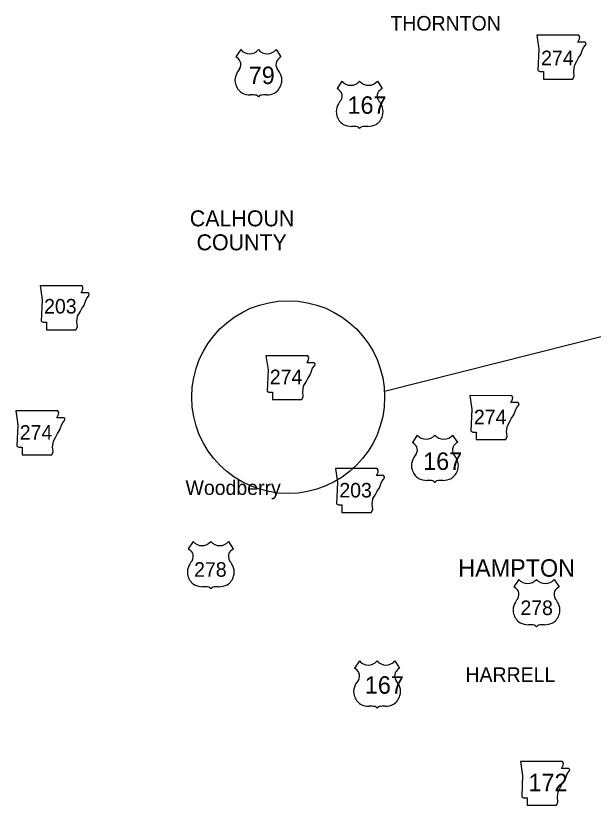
# Model space of a CAD drawing. Extents: x 172 to 3385, y 73 to 2074.
# Drawn here: x 198 to 834, y 1117 to 1987 of the extents above; entities that cross this region are included whole.
import ezdxf

# ---------------------------------------------------------------- set-up
doc = ezdxf.new("R2010")
doc.units = 0
for name, color, linetype in [('G-ANNO-NPLT', 7, 'Continuous'), ('Level 21', 7, 'Continuous'), ('Level 22', 7, 'Continuous'), ('Level 24', 7, 'Continuous'), ('R_Border', 7, 'Continuous'), ('R_Border Prem', 7, 'Continuous')]:
    doc.layers.add(name, color=color, linetype=linetype)

msp = doc.modelspace()

# ---------------------------------------------------------------- linework, layer by layer
at = {"layer": 'Level 21'}
for points in [[(771.57, 1965.87), (773.89, 1950.45), (772.86, 1927.07), (774.91, 1925.79), (778.77, 1925.79), (778.77, 1917.56), (811.15, 1917.56), (812.69, 1920.9), (812.17, 1926.3), (812.95, 1932.47), (815.77, 1937.35), (817.57, 1940.95), (820.14, 1944.8), (821.68, 1948.91), (822.97, 1952.25), (825.28, 1955.08), (825.79, 1956.88), (824.77, 1958.16), (816.8, 1958.16), (818.6, 1961.76), (818.86, 1964.07), (817.79, 1965.85)], [(224.33, 1689.68), (226.64, 1674.26), (225.61, 1650.88), (227.67, 1649.59), (231.52, 1649.59), (231.52, 1641.37), (263.9, 1641.37), (265.44, 1644.71), (264.93, 1650.11), (265.7, 1656.28), (268.53, 1661.16), (270.33, 1664.76), (272.9, 1668.61), (274.44, 1672.72), (275.72, 1676.06), (278.03, 1678.89), (278.55, 1680.69), (277.52, 1681.97), (269.55, 1681.97), (271.35, 1685.57), (271.61, 1687.88), (270.54, 1689.66)], [(473.18, 1612.6), (475.49, 1597.18), (474.46, 1573.8), (476.52, 1572.51), (480.37, 1572.51), (480.37, 1564.29), (512.75, 1564.29), (514.29, 1567.63), (513.78, 1573.03), (514.55, 1579.19), (517.37, 1584.07), (519.17, 1587.67), (521.74, 1591.53), (523.29, 1595.64), (524.57, 1598.98), (526.88, 1601.81), (527.4, 1603.6), (526.37, 1604.89), (518.4, 1604.89), (520.2, 1608.49), (520.46, 1610.8), (519.39, 1612.58)], [(697.73, 1568.72), (700.04, 1553.3), (699.01, 1529.92), (701.07, 1528.63), (704.92, 1528.63), (704.92, 1520.41), (737.3, 1520.41), (738.84, 1523.75), (738.33, 1529.14), (739.1, 1535.31), (741.93, 1540.19), (743.72, 1543.79), (746.29, 1547.65), (747.84, 1551.76), (749.12, 1555.1), (751.43, 1557.92), (751.95, 1559.72), (750.92, 1561.01), (742.95, 1561.01), (744.75, 1564.61), (745.01, 1566.92), (743.94, 1568.69)], [(197.6, 1551.94), (199.91, 1536.53), (198.89, 1513.14), (200.94, 1511.86), (204.8, 1511.86), (204.8, 1503.63), (237.17, 1503.63), (238.72, 1506.97), (238.2, 1512.37), (238.97, 1518.54), (241.8, 1523.42), (243.6, 1527.02), (246.17, 1530.87), (247.71, 1534.98), (248.99, 1538.32), (251.31, 1541.15), (251.82, 1542.95), (250.79, 1544.23), (242.83, 1544.23), (244.63, 1547.83), (244.88, 1550.14), (243.82, 1551.92)], [(549.65, 1488.36), (551.97, 1472.94), (550.94, 1449.56), (552.99, 1448.28), (556.85, 1448.28), (556.85, 1440.05), (589.23, 1440.05), (590.77, 1443.39), (590.25, 1448.79), (591.02, 1454.96), (593.85, 1459.84), (595.65, 1463.44), (598.22, 1467.29), (599.76, 1471.4), (601.05, 1474.74), (603.36, 1477.57), (603.87, 1479.37), (602.84, 1480.65), (594.88, 1480.65), (596.68, 1484.25), (596.93, 1486.56), (595.87, 1488.34)], [(753.63, 1165.68), (755.94, 1150.26), (754.91, 1126.88), (756.97, 1125.59), (760.82, 1125.59), (760.82, 1117.37), (793.2, 1117.37), (794.74, 1120.71), (794.23, 1126.11), (795, 1132.28), (797.83, 1137.16), (799.63, 1140.76), (802.2, 1144.61), (803.74, 1148.72), (805.02, 1152.06), (807.33, 1154.89), (807.85, 1156.69), (806.82, 1157.97), (798.85, 1157.97), (800.65, 1161.57), (800.91, 1163.88), (799.84, 1165.66)]]:
    msp.add_lwpolyline(points, close=True, dxfattribs=at)
at = {"layer": 'Level 22'}
for p, q in [((445.33, 1950.07), (440.07, 1941.94)), ((484.43, 1950.07), (489.68, 1941.94)), ((556.86, 1915.29), (551.6, 1907.15)), ((595.95, 1915.29), (601.21, 1907.15)), ((639.77, 1525.26), (634.51, 1517.13)), ((678.86, 1525.26), (684.12, 1517.13)), ((392.89, 1408), (387.63, 1399.87)), ((431.98, 1408), (437.24, 1399.87)), ((751.66, 1366.17), (746.4, 1358.03)), ((790.75, 1366.17), (796.01, 1358.03)), ((576.06, 1276.39), (570.8, 1268.25)), ((615.15, 1276.39), (620.41, 1268.25))]:
    msp.add_line(p, q, dxfattribs=at)
for centre, radius, start, end in [((455.12, 1958.31), 12.8, 220.07504, 319.67012), ((474.63, 1958.31), 12.8, 220.32988, 319.92496), ((433.2, 1930.13), 13.66, 30.7809, 59.98827), ((496.55, 1930.13), 13.66, 120.01173, 149.2191), ((436.21, 1933.74), 9.36, 328.81046, 21.21077), ((493.55, 1933.74), 9.36, 158.78923, 211.18954), ((460.7, 1914.54), 21.85, 138.95648, 162.69135), ((469.06, 1914.54), 21.85, 17.30865, 41.04352), ((453.49, 1916.33), 14.44, 160.95764, 197.38186), ((476.27, 1916.33), 14.44, 342.61814, 19.04236), ((566.65, 1923.52), 12.8, 220.07504, 319.67012), ((586.16, 1923.52), 12.8, 220.32988, 319.92496), ((455.84, 1916.37), 16.7, 195.10743, 237.13119), ((473.92, 1916.37), 16.7, 302.86881, 344.89257), ((544.73, 1895.35), 13.66, 30.7809, 59.98827), ((608.08, 1895.35), 13.66, 120.01173, 149.2191), ((456.15, 1921.63), 21.45, 244.07708, 269.57785), ((456.64, 1860.9), 39.29, 81.19416, 90.95387), ((461.56, 1896.13), 3.76, 28.03422, 72.98637), ((468.2, 1896.13), 3.76, 107.01363, 151.96578), ((473.11, 1860.9), 39.29, 89.04613, 98.80584), ((473.61, 1921.63), 21.45, 270.42215, 295.92292), ((547.73, 1898.95), 9.36, 328.81046, 21.21077), ((605.07, 1898.95), 9.36, 158.78923, 211.18954), ((572.22, 1879.76), 21.85, 138.95648, 162.69135), ((580.58, 1879.76), 21.85, 17.30865, 41.04352), ((565.01, 1881.55), 14.44, 160.95764, 197.38186), ((587.8, 1881.55), 14.44, 342.61814, 19.04236), ((567.36, 1881.59), 16.7, 195.10743, 237.13119), ((585.45, 1881.59), 16.7, 302.86881, 344.89257), ((567.67, 1886.85), 21.45, 244.07708, 269.57785), ((568.17, 1826.12), 39.29, 81.19416, 90.95387), ((573.08, 1861.34), 3.76, 28.03422, 72.98637), ((579.73, 1861.34), 3.76, 107.01363, 151.96578), ((584.64, 1826.12), 39.29, 89.04613, 98.80584), ((585.13, 1886.85), 21.45, 270.42215, 295.92292), ((649.56, 1533.5), 12.8, 220.07504, 319.67012), ((669.07, 1533.5), 12.8, 220.32988, 319.92496), ((627.64, 1505.33), 13.66, 30.7809, 59.98827), ((690.99, 1505.33), 13.66, 120.01173, 149.2191), ((630.65, 1508.93), 9.36, 328.81046, 21.21077), ((687.98, 1508.93), 9.36, 158.78923, 211.18954), ((655.13, 1489.73), 21.85, 138.95648, 162.69135), ((663.5, 1489.73), 21.85, 17.30865, 41.04352), ((647.92, 1491.52), 14.44, 160.95764, 197.38186), ((670.71, 1491.52), 14.44, 342.61814, 19.04236), ((650.27, 1491.57), 16.7, 195.10743, 237.13119), ((668.36, 1491.57), 16.7, 302.86881, 344.89257), ((650.58, 1496.83), 21.45, 244.07708, 269.57785), ((651.08, 1436.1), 39.29, 81.19416, 90.95387), ((655.99, 1471.32), 3.76, 28.03422, 72.98637), ((662.64, 1471.32), 3.76, 107.01363, 151.96578), ((667.55, 1436.1), 39.29, 89.04613, 98.80584), ((668.05, 1496.83), 21.45, 270.42215, 295.92292), ((402.68, 1416.24), 12.8, 220.07504, 319.67012), ((422.19, 1416.24), 12.8, 220.32988, 319.92496), ((380.76, 1388.07), 13.66, 30.7809, 59.98827), ((383.77, 1391.67), 9.36, 328.81046, 21.21077), ((441.11, 1391.67), 9.36, 158.78923, 211.18954), ((444.11, 1388.07), 13.66, 120.01173, 149.2191), ((408.25, 1372.47), 21.85, 138.95648, 162.69135), ((416.62, 1372.47), 21.85, 17.30865, 41.04352), ((401.04, 1374.26), 14.44, 160.95764, 197.38186), ((423.83, 1374.26), 14.44, 342.61814, 19.04236), ((403.39, 1374.31), 16.7, 195.10743, 237.13119), ((421.48, 1374.31), 16.7, 302.86881, 344.89257), ((761.45, 1374.4), 12.8, 220.07504, 319.67012), ((780.96, 1374.4), 12.8, 220.32988, 319.92496), ((403.7, 1379.57), 21.45, 244.07708, 269.57785), ((404.2, 1318.84), 39.29, 81.19416, 90.95387), ((409.11, 1354.06), 3.76, 28.03422, 72.98637), ((415.76, 1354.06), 3.76, 107.01363, 151.96578), ((420.67, 1318.84), 39.29, 89.04613, 98.80584), ((421.17, 1379.57), 21.45, 270.42215, 295.92292), ((739.53, 1346.23), 13.66, 30.7809, 59.98827), ((802.88, 1346.23), 13.66, 120.01173, 149.2191), ((742.53, 1349.83), 9.36, 328.81046, 21.21077), ((799.87, 1349.83), 9.36, 158.78923, 211.18954), ((767.02, 1330.64), 21.85, 138.95648, 162.69135), ((775.38, 1330.64), 21.85, 17.30865, 41.04352), ((759.81, 1332.43), 14.44, 160.95764, 197.38186), ((782.6, 1332.43), 14.44, 342.61814, 19.04236), ((762.16, 1332.47), 16.7, 195.10743, 237.13119), ((780.25, 1332.47), 16.7, 302.86881, 344.89257), ((762.47, 1337.73), 21.45, 244.07708, 269.57785), ((762.97, 1277), 39.29, 81.19416, 90.95387), ((767.88, 1312.22), 3.76, 28.03422, 72.98637), ((774.53, 1312.22), 3.76, 107.01363, 151.96578), ((779.44, 1277), 39.29, 89.04613, 98.80584), ((779.93, 1337.73), 21.45, 270.42215, 295.92292), ((585.85, 1284.62), 12.8, 220.07504, 319.67012), ((605.36, 1284.62), 12.8, 220.32988, 319.92496), ((563.93, 1256.45), 13.66, 30.7809, 59.98827), ((566.94, 1260.05), 9.36, 328.81046, 21.21077), ((624.28, 1260.05), 9.36, 158.78923, 211.18954), ((627.28, 1256.45), 13.66, 120.01173, 149.2191), ((591.43, 1240.86), 21.85, 138.95648, 162.69135), ((599.79, 1240.86), 21.85, 17.30865, 41.04352), ((584.21, 1242.65), 14.44, 160.95764, 197.38186), ((607, 1242.65), 14.44, 342.61814, 19.04236), ((586.56, 1242.69), 16.7, 195.10743, 237.13119), ((604.65, 1242.69), 16.7, 302.86881, 344.89257), ((586.88, 1247.95), 21.45, 244.07708, 269.57785), ((604.34, 1247.95), 21.45, 270.42215, 295.92292), ((587.37, 1187.22), 39.29, 81.19416, 90.95387), ((592.28, 1222.44), 3.76, 28.03422, 72.98637), ((598.93, 1222.44), 3.76, 107.01363, 151.96578), ((603.84, 1187.22), 39.29, 89.04613, 98.80584)]:
    msp.add_arc(centre, radius, start, end, dxfattribs=at)
at = {"layer": 'R_Border Prem'}
msp.add_lwpolyline([(603.86, 1573.8), (1018.61, 1678.41), (1236.26, 1678.41)], dxfattribs=at)
msp.add_circle((497.68, 1567.07), 106.26, dxfattribs=at)

# ---------------------------------------------------------------- texts
at = {"layer": 'G-ANNO-NPLT'}
for s, height, p in [('THORNTON', 16.04, (610.31, 1971.05)), ('HAMPTON', 19.247, (684.97, 1369.18)), ('HARRELL', 16.04, (692.96, 1253.31))]:
    msp.add_text(s, height=height, dxfattribs=at).set_placement(p)
at = {"layer": 'Level 21'}
for s, height, p in [('274', 16.04, (776.33, 1932.88)), ('203', 16.04, (228.79, 1659.22)), ('274', 16.04, (477.44, 1581.34)), ('274', 16.04, (702.29, 1537.14)), ('274', 16.04, (201.97, 1520.17)), ('203', 16.04, (554.03, 1456.5)), ('172', 19.247, (762.42, 1132.81))]:
    msp.add_text(s, height=height, dxfattribs=at).set_placement(p)
at = {"layer": 'Level 22'}
for s, height, p in [('79', 19.247, (454.25, 1912.08)), ('167', 19.247, (563.06, 1879.32)), ('167', 19.247, (646.41, 1486.87)), ('278', 16.04, (394.08, 1369.14)), ('278', 16.04, (753.5, 1326.93)), ('167', 19.247, (582.15, 1240.25))]:
    msp.add_text(s, height=height, dxfattribs=at).set_placement(p)
at = {"layer": 'Level 24'}
msp.add_text('Woodberry', height=16.04, dxfattribs=at).set_placement((384.59, 1459.31))
at = {"layer": 'R_Border'}
for s, p in [('CALHOUN', (389.31, 1755.3)), ('COUNTY', (396.73, 1728.89))]:
    msp.add_text(s, height=17.61, dxfattribs=at).set_placement(p)

doc.saveas('drawing.dxf')
